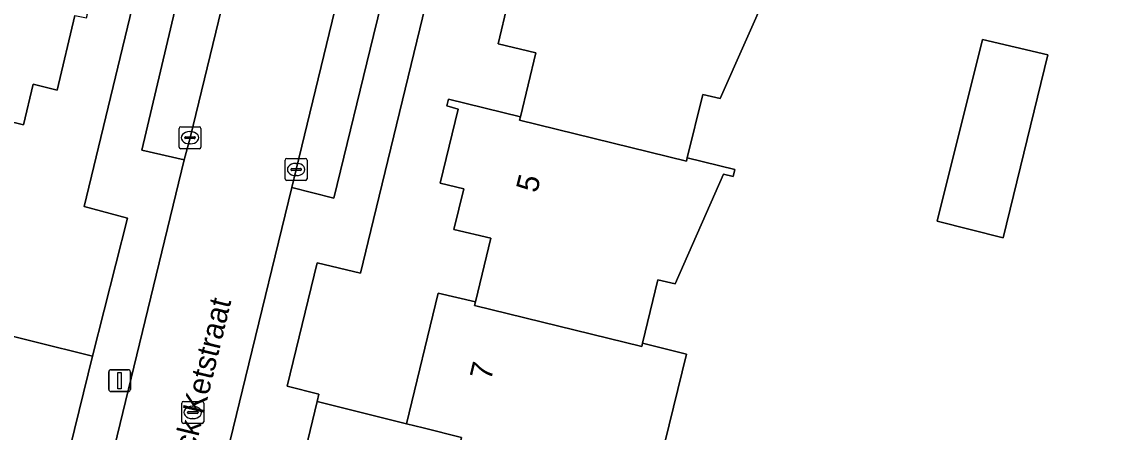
# Model space of a CAD drawing. Extents: x 163266 to 164362, y 381528 to 382286.
# Drawn here: x 163983.95 to 164033.14, y 382153.93 to 382172.66 of the extents above; entities that cross this region are included whole.
import ezdxf

# ---------------------------------------------------------------- set-up
doc = ezdxf.new("R2010")
doc.units = 0
for name, color, linetype in [('IMGEO_Erf', 7, 'Continuous'), ('IMGEO_Groenvoorziening', 7, 'Continuous'), ('IMGEO_Kolk', 7, 'Continuous'), ('IMGEO_Lichtmast', 7, 'Continuous'), ('IMGEO_Openbare_ruimte_label', 7, 'Continuous'), ('IMGEO_Pand', 7, 'Continuous'), ('IMGEO_Pand_nummerreeks', 7, 'Continuous'), ('IMGEO_Parkeervlak_open', 7, 'Continuous'), ('IMGEO_Rijbaan_lokaal_open', 7, 'Continuous'), ('IMGEO_Rioolput', 7, 'Continuous'), ('IMGEO_Voetpad_open', 7, 'Continuous')]:
    doc.layers.add(name, color=color, linetype=linetype)

msp = doc.modelspace()

# ---------------------------------------------------------------- linework, layer by layer
at = {"layer": 'IMGEO_Erf'}
for points in [[(163986.374, 382172.941), (163985.564, 382169.537), (163984.478, 382169.808), (163984.037, 382167.955), (163982.343, 382168.367), (163981.632, 382165.482), (163981.594, 382165.327), (163983.291, 382164.92), (163981.87, 382159.091), (163981.786, 382158.745), (163987.189, 382157.409), (163988.786, 382163.698), (163986.799, 382164.233), (163992.502, 382187.822)], [(164005.136, 382184.782), (164000, 382163.638), (163999.404, 382161.184), (163997.432, 382161.663), (163996.065, 382156.032), (163997.504, 382155.67), (163997.423, 382155.335), (164001.499, 382154.321), (164002.947, 382160.282), (164004.643, 382159.875), (164005.353, 382162.779), (164003.657, 382163.186), (164004.12, 382165.026), (164003.035, 382165.292), (164003.86, 382168.673), (164003.335, 382168.819), (164003.411, 382169.122), (164006.695, 382168.321), (164007.391, 382171.233), (164005.681, 382171.642), (164006.125, 382173.498)], [(164018.029, 382174.164), (164015.811, 382169.146), (164015.014, 382169.341), (164014.306, 382166.446), (164016.471, 382165.913), (164016.395, 382165.602), (164015.958, 382165.709), (164013.752, 382160.695), (164012.956, 382160.886), (164012.262, 382157.994), (164014.262, 382157.5), (164012.113, 382148.694), (164008.835, 382149.494), (164008.56, 382148.37), (164034.127, 382142.141)]]:
    msp.add_lwpolyline(points, dxfattribs=at)
msp.add_lwpolyline([(164028.706, 382162.801), (164025.699, 382163.554), (164027.769, 382171.841), (164030.739, 382171.145)], close=True, dxfattribs=at)
at = {"layer": 'IMGEO_Groenvoorziening'}
for points in [[(163984.939, 382148.237), (163987.189, 382157.409), (163981.786, 382158.745), (163981.87, 382159.091), (163979.376, 382159.691), (163978.207, 382154.83), (163980.056, 382154.007), (163981.009, 382153.693), (163980.472, 382152.456), (163979.265, 382149.679), (163976.291, 382148.293), (163946.766, 382155.398), (163926.96, 382160.131), (163910.282, 382164.245), (163879.481, 382171.844), (163877.887, 382175.562)], [(164000.24, 382153.408), (164001.02, 382153.536), (164001.662, 382153.515), (164003.846, 382153.01), (164004.011, 382153.696), (164002.267, 382154.13), (164001.499, 382154.321), (163997.423, 382155.335), (163991.266, 382129.819), (163990.325, 382125.944), (163992.505, 382125.353)]]:
    msp.add_lwpolyline(points, dxfattribs=at)
at = {"layer": 'IMGEO_Kolk'}
for p, q in [((163991.128, 382166.938), (163991.128, 382167.79)), ((163991.203, 382167.864), (163992.055, 382167.864)), ((163991.616, 382167.644), (163991.641, 382167.644)), ((163992.129, 382167.79), (163992.129, 382166.938)), ((163991.387, 382167.358), (163991.387, 382167.37)), ((163991.825, 382167.321), (163991.427, 382167.321)), ((163991.43, 382167.407), (163991.828, 382167.407)), ((163991.639, 382167.084), (163991.614, 382167.084)), ((163991.871, 382167.37), (163991.871, 382167.358)), ((163992.055, 382166.864), (163991.203, 382166.864)), ((163995.967, 382165.49), (163995.967, 382166.342)), ((163996.042, 382166.416), (163996.894, 382166.416)), ((163996.455, 382166.196), (163996.48, 382166.196)), ((163996.968, 382166.342), (163996.968, 382165.49)), ((163996.226, 382165.91), (163996.226, 382165.922)), ((163996.664, 382165.873), (163996.266, 382165.873)), ((163996.269, 382165.959), (163996.667, 382165.959)), ((163996.478, 382165.636), (163996.453, 382165.636)), ((163996.71, 382165.922), (163996.71, 382165.91)), ((163996.894, 382165.416), (163996.042, 382165.416))]:
    msp.add_line(p, q, dxfattribs=at)
for points in [[(163991.128, 382166.938), (163991.128, 382167.79)], [(163991.203, 382167.864), (163992.055, 382167.864)], [(163992.129, 382167.79), (163992.129, 382166.938)], [(163992.055, 382166.864), (163991.203, 382166.864)], [(163995.967, 382165.49), (163995.967, 382166.342)], [(163996.042, 382166.416), (163996.894, 382166.416)], [(163996.968, 382166.342), (163996.968, 382165.49)], [(163996.894, 382165.416), (163996.042, 382165.416)]]:
    msp.add_lwpolyline(points, dxfattribs=at)
for centre, radius, start, end in [((163991.205, 382167.788), 0.0765, 91.552, 178.448), ((163991.205, 382167.788), 0.0765, 91.552, 178.448), ((163992.053, 382167.788), 0.0765, 1.552, 88.448), ((163992.053, 382167.788), 0.0765, 1.552, 88.448), ((163991.427, 382167.367), 0.0403, 85.8775, 175.7526), ((163991.424, 382167.357), 0.0366, 178.938, 274.7102), ((163991.828, 382167.364), 0.043, 264.8664, 352.4533), ((163991.832, 382167.369), 0.0386, 1.7309, 96.639), ((163991.205, 382166.94), 0.0765, 181.552, 268.448), ((163991.205, 382166.94), 0.0765, 181.552, 268.448), ((163992.053, 382166.94), 0.0765, 271.552, 358.448), ((163992.053, 382166.94), 0.0765, 271.552, 358.448), ((163996.044, 382166.34), 0.0765, 91.552, 178.448), ((163996.044, 382166.34), 0.0765, 91.552, 178.448), ((163996.892, 382166.34), 0.0765, 1.552, 88.448), ((163996.892, 382166.34), 0.0765, 1.552, 88.448), ((163996.266, 382165.919), 0.0403, 85.8775, 175.7526), ((163996.263, 382165.909), 0.0366, 178.938, 274.7102), ((163996.667, 382165.916), 0.043, 264.8664, 352.4533), ((163996.671, 382165.921), 0.0386, 1.7309, 96.639), ((163996.044, 382165.492), 0.0765, 181.552, 268.448), ((163996.044, 382165.492), 0.0765, 181.552, 268.448), ((163996.892, 382165.492), 0.0765, 271.552, 358.448), ((163996.892, 382165.492), 0.0765, 271.552, 358.448)]:
    msp.add_arc(centre, radius, start, end, dxfattribs=at)
for centre, major_axis, ratio, start_param, end_param in [((163991.615, 382167.364), (-0.387, 0.002), 0.722429, 4.712389, 7.853982), ((163991.64, 382167.364), (-0.39, 0.002), 0.717154, 1.570796, 4.712389), ((163996.454, 382165.916), (-0.387, 0.002), 0.722429, 4.712389, 7.853982), ((163996.479, 382165.916), (-0.39, 0.002), 0.717154, 1.570796, 4.712389)]:
    msp.add_ellipse(centre, major_axis=major_axis, ratio=ratio, start_param=start_param, end_param=end_param, dxfattribs=at)
at = {"layer": 'IMGEO_Lichtmast'}
for p, q in [((163988.023, 382156.789), (163988.813, 382156.789)), ((163988.813, 382156.789), (163988.023, 382156.789)), ((163987.923, 382155.889), (163987.923, 382156.689)), ((163987.923, 382156.689), (163987.923, 382155.889)), ((163988.913, 382156.689), (163988.913, 382155.889)), ((163988.913, 382155.889), (163988.913, 382156.689)), ((163988.813, 382155.789), (163988.023, 382155.789)), ((163988.023, 382155.789), (163988.813, 382155.789))]:
    msp.add_line(p, q, dxfattribs=at)
msp.add_lwpolyline([(163988.343, 382156.664), (163988.493, 382156.664), (163988.493, 382155.914), (163988.343, 382155.914), (163988.343, 382156.664)], dxfattribs=at)
for centre, start, end in [((163988.023, 382156.689), 90, 180), ((163988.023, 382156.689), 90, 180), ((163988.813, 382156.689), 0, 90), ((163988.813, 382156.689), 360, 90), ((163988.023, 382155.889), 180, 270), ((163988.023, 382155.889), 180, 270), ((163988.813, 382155.889), 270, 0), ((163988.813, 382155.889), 270, 0)]:
    msp.add_arc(centre, 0.1, start, end, dxfattribs=at)
at = {"layer": 'IMGEO_Pand'}
for points in [[(164018.029, 382174.164), (164018.466, 382174.055), (164018.543, 382174.366), (164018.108, 382174.473), (164016.378, 382174.9), (164016.34, 382174.745), (164008.725, 382176.623), (164008.762, 382176.779), (164005.468, 382177.575), (164005.39, 382177.273), (164005.93, 382177.131), (164005.109, 382173.741), (164006.125, 382173.498), (164005.681, 382171.642), (164007.391, 382171.233), (164006.695, 382168.321), (164006.658, 382168.165), (164014.268, 382166.291), (164014.306, 382166.446), (164015.014, 382169.341), (164015.811, 382169.146)], [(163986.374, 382172.941), (163986.908, 382172.825), (163986.958, 382172.999), (163983.646, 382173.792), (163976.049, 382175.61), (163973.891, 382176.127), (163973.853, 382175.971), (163974.29, 382175.865), (163973.941, 382170.399), (163974.74, 382170.206), (163974.04, 382167.303), (163974.002, 382167.147), (163981.594, 382165.327), (163981.632, 382165.482), (163982.343, 382168.367), (163984.037, 382167.955), (163984.478, 382169.808), (163985.564, 382169.537)], [(164028.706, 382162.801), (164030.739, 382171.145), (164027.769, 382171.841), (164025.699, 382163.554)], [(164014.306, 382166.446), (164014.268, 382166.291), (164006.658, 382168.165), (164006.695, 382168.321), (164003.411, 382169.122), (164003.335, 382168.819), (164003.86, 382168.673), (164003.035, 382165.292), (164004.12, 382165.026), (164003.657, 382163.186), (164005.353, 382162.779), (164004.643, 382159.875), (164004.605, 382159.72), (164012.225, 382157.838), (164012.262, 382157.994), (164012.956, 382160.886), (164013.752, 382160.695), (164015.958, 382165.709), (164016.395, 382165.602), (164016.471, 382165.913)], [(164002.267, 382154.13), (164004.011, 382153.696), (164003.846, 382153.01), (164003.07, 382149.793), (164002.843, 382148.849), (164008.347, 382147.496), (164008.56, 382148.37), (164008.835, 382149.494), (164012.113, 382148.694), (164014.262, 382157.5), (164012.262, 382157.994), (164012.225, 382157.838), (164004.605, 382159.72), (164004.643, 382159.875), (164002.947, 382160.282), (164001.499, 382154.321)]]:
    msp.add_lwpolyline(points, close=True, dxfattribs=at)
at = {"layer": 'IMGEO_Parkeervlak_open'}
for points in [[(163994.702, 382184.239), (163993.606, 382184.505), (163989.433, 382166.803), (163991.364, 382166.35), (163991.629, 382167.364), (163995.534, 382183.397)], [(164000.785, 382183.699), (164000.358, 382181.925), (164000, 382180.452), (163996.467, 382165.917), (163996.272, 382165.101), (163998.191, 382164.613), (164000, 382172.02), (164002.517, 382182.327), (164001.548, 382182.559)]]:
    msp.add_lwpolyline(points, dxfattribs=at)
at = {"layer": 'IMGEO_Rijbaan_lokaal_open'}
msp.add_lwpolyline([(163987.167, 382149.079), (163992.073, 382147.878), (163992.131, 382148.084), (163993.185, 382152.428), (163994.157, 382156.433), (163996.272, 382165.101), (163996.467, 382165.917), (164000, 382180.452), (164000.358, 382181.925), (164000.785, 382183.699), (164000.857, 382184.071), (164000, 382184.28), (163995.998, 382185.255), (163995.905, 382184.866), (163995.534, 382183.397), (163991.629, 382167.364), (163991.364, 382166.35)], close=True, dxfattribs=at)
at = {"layer": 'IMGEO_Rioolput'}
for p, q in [((163991.252, 382154.414), (163991.252, 382155.266)), ((163991.327, 382155.34), (163992.179, 382155.34)), ((163992.253, 382155.266), (163992.253, 382154.414)), ((163991.511, 382154.834), (163991.511, 382154.846)), ((163991.949, 382154.797), (163991.551, 382154.797)), ((163991.554, 382154.883), (163991.952, 382154.883)), ((163991.74, 382155.12), (163991.765, 382155.12)), ((163991.995, 382154.846), (163991.995, 382154.834)), ((163992.179, 382154.34), (163991.327, 382154.34)), ((163991.763, 382154.56), (163991.738, 382154.56))]:
    msp.add_line(p, q, dxfattribs=at)
for points in [[(163991.252, 382154.414), (163991.252, 382155.266)], [(163991.327, 382155.34), (163992.179, 382155.34)], [(163992.253, 382155.266), (163992.253, 382154.414)], [(163992.179, 382154.34), (163991.327, 382154.34)]]:
    msp.add_lwpolyline(points, dxfattribs=at)
for centre, radius, start, end in [((163991.329, 382155.264), 0.0765, 91.552, 178.448), ((163991.329, 382155.264), 0.0765, 91.552, 178.448), ((163992.177, 382155.264), 0.0765, 1.552, 88.448), ((163992.177, 382155.264), 0.0765, 1.552, 88.448), ((163991.551, 382154.843), 0.0403, 85.8775, 175.7526), ((163991.548, 382154.833), 0.0366, 178.938, 274.7102), ((163991.952, 382154.84), 0.043, 264.8664, 352.4533), ((163991.956, 382154.845), 0.0386, 1.7309, 96.639), ((163991.329, 382154.416), 0.0765, 181.552, 268.448), ((163991.329, 382154.416), 0.0765, 181.552, 268.448), ((163992.177, 382154.416), 0.0765, 271.552, 358.448), ((163992.177, 382154.416), 0.0765, 271.552, 358.448)]:
    msp.add_arc(centre, radius, start, end, dxfattribs=at)
for centre, major_axis, ratio, start_param, end_param in [((163991.739, 382154.84), (-0.387, 0.002), 0.722429, 4.712389, 7.853982), ((163991.764, 382154.84), (-0.39, 0.002), 0.717154, 1.570796, 4.712389)]:
    msp.add_ellipse(centre, major_axis=major_axis, ratio=ratio, start_param=start_param, end_param=end_param, dxfattribs=at)
at = {"layer": 'IMGEO_Voetpad_open'}
for points in [[(163992.502, 382187.822), (163986.799, 382164.233), (163988.786, 382163.698), (163987.189, 382157.409), (163984.939, 382148.237)], [(163988.373, 382117.903), (163990.325, 382125.944), (163991.266, 382129.819), (163997.423, 382155.335), (163997.504, 382155.67), (163996.065, 382156.032), (163997.432, 382161.663), (163999.404, 382161.184), (164000, 382163.638), (164005.136, 382184.782)], [(163986.848, 382147.81), (163987.167, 382149.079), (163991.364, 382166.35), (163989.433, 382166.803), (163993.606, 382184.505)], [(164001.548, 382182.559), (164002.517, 382182.327), (164000, 382172.02), (163998.191, 382164.613), (163996.272, 382165.101), (163994.157, 382156.433), (163993.185, 382152.428), (163994.78, 382152.018), (163993.661, 382147.394), (163991.566, 382138.736), (163990.91, 382136.027), (163989.485, 382130.141), (163988.127, 382124.539), (163986.505, 382117.847), (163986.458, 382117.654)]]:
    msp.add_lwpolyline(points, dxfattribs=at)

# ---------------------------------------------------------------- texts
at = {"layer": 'IMGEO_Openbare_ruimte_label'}
msp.add_text('Dick Ketstraat', height=1, rotation=76.3528, dxfattribs=at).set_placement((163991.551, 382151.827))
at = {"layer": 'IMGEO_Pand_nummerreeks'}
for s, rotation, p in [('5', 75.8759, (164007.449, 382164.811)), ('7', 76.3466, (164005.345, 382156.259))]:
    msp.add_text(s, height=1, rotation=rotation, dxfattribs=at).set_placement(p)

doc.saveas('drawing.dxf')
